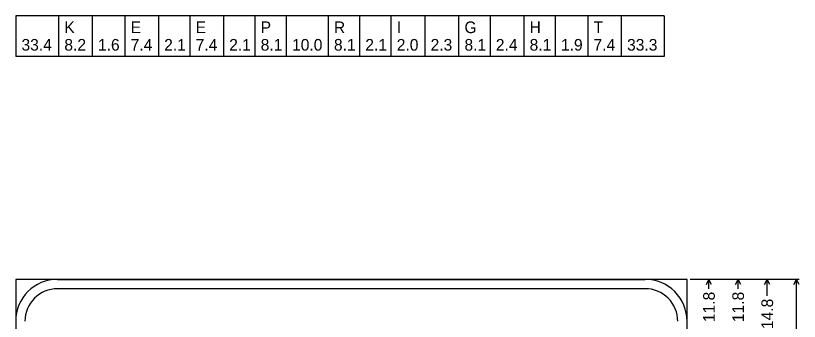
# Model space of a CAD drawing. Extents: x 1820207 to 1820557, y 740216 to 740315.
# Drawn here: x 1820477.35 to 1820484.35, y 740229.87 to 740232.6 of the extents above; entities that cross this region are included whole.
import ezdxf

# ---------------------------------------------------------------- set-up
doc = ezdxf.new("R2010")
doc.units = 0
doc.layers.add('SC_Scratch3', color=7, linetype='Continuous')

msp = doc.modelspace()

# ---------------------------------------------------------------- linework, layer by layer
at = {"layer": 'SC_Scratch3'}
for p, q in [((1820477.351, 740232.5997), (1820477.351, 740232.2352)), ((1820483.1461, 740232.5997), (1820477.351, 740232.5997)), ((1820477.7338, 740232.5997), (1820477.7338, 740232.2352)), ((1820478.0343, 740232.5997), (1820478.0343, 740232.2352)), ((1820478.3266, 740232.5997), (1820478.3266, 740232.2352)), ((1820478.626, 740232.5997), (1820478.626, 740232.2352)), ((1820478.9075, 740232.5997), (1820478.9075, 740232.2352)), ((1820479.2069, 740232.5997), (1820479.2069, 740232.2352)), ((1820479.4883, 740232.5997), (1820479.4883, 740232.2352)), ((1820479.7686, 740232.5997), (1820479.7686, 740232.2352)), ((1820480.1427, 740232.5997), (1820480.1427, 740232.2352)), ((1820480.423, 740232.5997), (1820480.423, 740232.2352)), ((1820480.7045, 740232.5997), (1820480.7045, 740232.2352)), ((1820481.0066, 740232.5997), (1820481.0066, 740232.2352)), ((1820481.3093, 740232.5997), (1820481.3093, 740232.2352)), ((1820481.5896, 740232.5997), (1820481.5896, 740232.2352)), ((1820481.8912, 740232.5997), (1820481.8912, 740232.2352)), ((1820482.1715, 740232.5997), (1820482.1715, 740232.2352)), ((1820482.4627, 740232.5997), (1820482.4627, 740232.2352)), ((1820482.7622, 740232.5997), (1820482.7622, 740232.2352)), ((1820483.1461, 740232.5997), (1820483.1461, 740232.2352)), ((1820483.1461, 740232.2352), (1820477.351, 740232.2352)), ((1820484.3535, 740230.2431), (1820483.377, 740230.2431)), ((1820483.5723, 740230.2431), (1820483.416, 740230.2431)), ((1820483.523, 740230.1965), (1820483.5463, 740230.2431)), ((1820483.5463, 740230.1578), (1820483.5463, 740230.2431)), ((1820483.5696, 740230.1965), (1820483.5463, 740230.2431)), ((1820483.8327, 740230.2431), (1820483.6765, 740230.2431)), ((1820483.7834, 740230.1965), (1820483.8067, 740230.2431)), ((1820483.8067, 740230.1578), (1820483.8067, 740230.2431)), ((1820483.83, 740230.1965), (1820483.8067, 740230.2431)), ((1820484.0931, 740230.2431), (1820483.9369, 740230.2431)), ((1820484.0438, 740230.1965), (1820484.0671, 740230.2431)), ((1820484.0671, 740230.0953), (1820484.0671, 740230.2431)), ((1820484.0904, 740230.1965), (1820484.0671, 740230.2431)), ((1820484.3042, 740230.1965), (1820484.3275, 740230.2431)), ((1820484.3275, 740228.5963), (1820484.3275, 740230.2431)), ((1820484.3508, 740230.1965), (1820484.3275, 740230.2431))]:
    msp.add_line(p, q, dxfattribs=at)
for points in [[(1820477.351, 740226.7431), (1820483.351, 740226.7431), (1820483.351, 740230.2431), (1820477.351, 740230.2431), (1820477.351, 740226.7431), (1820477.351, 740226.7431), (1820477.351, 740226.7431)], [(1820477.726, 740230.2431), (1820482.976, 740230.2431)], [(1820482.976, 740230.1597), (1820477.726, 740230.1597)], [(1820482.976, 740230.1597), (1820482.976, 740230.1597), (1820482.976, 740230.1597)]]:
    msp.add_lwpolyline(points, dxfattribs=at)
for centre, radius, start, end in [((1820477.726, 740229.8681), 0.375, 90.00021, 179.99985), ((1820482.976, 740229.8681), 0.375, 0, 90.00021), ((1820477.726, 740229.8681), 0.2917, 90.00021, 179.99985), ((1820482.976, 740229.8681), 0.2917, 0, 90.00021)]:
    msp.add_arc(centre, radius, start, end, dxfattribs=at)

# ---------------------------------------------------------------- texts
for s, height, p in [('K', 0.1042, (1820477.7859, 740232.4435)), ('E', 0.1042, (1820478.3787, 740232.4435)), ('E', 0.1042, (1820478.9595, 740232.4435)), ('P', 0.1042, (1820479.5404, 740232.4435)), ('R', 0.1042, (1820480.1948, 740232.4435)), ('I', 0.1042, (1820480.7565, 740232.4435)), ('G', 0.1042, (1820481.3614, 740232.4435)), ('H', 0.1042, (1820481.9433, 740232.4435)), ('T', 0.1042, (1820482.5148, 740232.4435)), ('33.4', 0.10417, (1820477.403, 740232.2872)), ('8.2', 0.10417, (1820477.7859, 740232.2872)), ('1.6', 0.10417, (1820478.0864, 740232.2872)), ('2.1', 0.10417, (1820478.6781, 740232.2872)), ('2.1', 0.10417, (1820479.259, 740232.2872)), ('8.1', 0.10417, (1820479.5404, 740232.2872)), ('10.0', 0.10417, (1820479.8207, 740232.2872)), ('8.1', 0.10417, (1820480.1948, 740232.2872)), ('2.1', 0.10417, (1820480.4751, 740232.2872)), ('2.0', 0.10417, (1820480.7565, 740232.2872)), ('2.3', 0.10417, (1820481.0587, 740232.2872)), ('8.1', 0.10417, (1820481.3614, 740232.2872)), ('2.4', 0.10417, (1820481.6417, 740232.2872)), ('8.1', 0.10417, (1820481.9433, 740232.2872)), ('1.9', 0.10417, (1820482.2236, 740232.2872)), ('33.3', 0.10417, (1820482.8142, 740232.2872)), ('7.4', 0.10417, (1820478.3787, 740232.2872)), ('7.4', 0.10417, (1820478.9595, 740232.2872)), ('7.4', 0.10417, (1820482.5148, 740232.2872))]:
    msp.add_text(s, height=height, dxfattribs=at).set_placement(p)
for s, p in [('11.8', (1820483.5984, 740229.8613)), ('11.8', (1820483.8588, 740229.8613)), ('14.8', (1820484.1192, 740229.7988))]:
    msp.add_text(s, height=0.10417, rotation=90.00021, dxfattribs=at).set_placement(p)

doc.saveas('drawing.dxf')
